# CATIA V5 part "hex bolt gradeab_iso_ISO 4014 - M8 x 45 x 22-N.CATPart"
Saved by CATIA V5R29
Part number: hex bolt gradeab_iso_ISO 4014 - M8 x 45 x 22-N
Revision: HERHANG?
Definition: B??MEYEN
Nomenclature: hex bolt gradeab_iso_ISO 4014 - M8 x 45 x 22-N
Source: Unknown
Bounding box of the stored display mesh (mm): x 0 to 50.3, y -7.506 to 7.506, z -6.5 to 6.5
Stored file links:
  C:\Users\제5강의실-27\Desktop\가치같이_내작업\hex bolt gradeab_iso_ISO 4014 - M8 x 45 x 22-N.CATPart
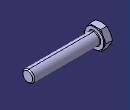
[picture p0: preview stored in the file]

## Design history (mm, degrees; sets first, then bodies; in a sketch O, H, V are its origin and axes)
Body1 "HeadFillet" (main body)
  Solid1: solid without history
